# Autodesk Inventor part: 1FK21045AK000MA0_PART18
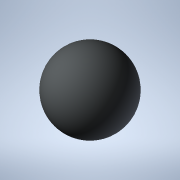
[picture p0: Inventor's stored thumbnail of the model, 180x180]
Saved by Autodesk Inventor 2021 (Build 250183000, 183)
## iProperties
Created: 2025-04
Part Number: 1FK21045AK000MA0_PART18
Material: Generic
Catalog Web Link: www.3dfindit.com
Description: -Servo synchronous motor
Document SubType Name: Modeling
Designer: psAdmin
Mass: 0.137258 g
Surface Area: 1.2868 cm^2
Volume: 0.137258 cm^3
Density: 1 g/cm^3
Appearance: PSOLRGB-212-217-219
Category: PARTsolutions
Title: 1FK21045AK000MA0_PART18
Author: Cadenas PARTsolutions
Comments: Servo synchronous motor
Sending System: PARTsolutions
Preprocessor: ST-DEVELOPER v19.3
PSOL_IDENT_0: {$CADENAS_DATA/23d-libs/siemens_ag/_cat_/3d/2f/1fk21045ak000ma0.prj},216 {VTYP=3D},{NB=1FK21045AK000
PSOL_IDENT_1: MA0_PART18},{LINA=1FK21045AK000MA0_PART18},{NN=1FK21045AK000MA0_PART18},{NOPRJ=TRUE},{DATE=19.08.202
PSOL_IDENT_2: 5 14:00:34},{GEOMDATE=30.07.2025 02:01:24},{VERSION=},{LINEID=10},{WBVAR=},{WBNUMERIC=}  {NB=1FK2104
PSOL_IDENT_3: 5AK000MA0_PART18},{LINA=1FK21045AK000MA0_PART18},{KT=DUMMY},{PREVIEW=../../../_pool_/a9/69/p_d211_xx
PSOL_IDENT_4: _00818j.png},{DESCSHORT=SIMOTICS S-1FK2 HD, SINAMICS S210 3AC 400V-480V, 1.7 Nm, 6000 rpm},{DESCLONG=
PSOL_IDENT_5: SIMOTICS S-1FK2 HD servo motor M0=2.4 Nm; PN = 1.07 kW at nN=6000 rpm (380-480 V); PN = 0.75 kW at n
PSOL_IDENT_6: N=3000 rpm (200-240 V); degree of protection IP64; cylindrical shaft D19x40mm; absolute encoder 22-b
PSOL_IDENT_7: it + 12-bit multiturn (encoder AM22DQC); with OCC interface; plug size M17, rotatable; SIMOTICS S-1F
PSOL_IDENT_8: K2 servomotorfor a wide range of uses in industrial environments. SIMOTICS S‑1FK2 servomotors are co
PSOL_IDENT_9: mpact synchronous motors with a high dynamic performance that set themselves apart as a result of th
PSOL_IDENT_10: eir high power density, degree of protection and overload capability. The motors are available in tw
PSOL_IDENT_11: o variants: as High Dynamic variant (highest dynamic performance as a result of the low intrinsic mo
PSOL_IDENT_12: ment of inertia for applications demanding a high dynamic performance with low moved masses) - and a
PSOL_IDENT_13: s Compact variant (precise and stable closed-loop control for medium up to large moved masses as a r
PSOL_IDENT_14: esult of a medium intrinsic moment of inertia). SIMOTICSS‑1FK2 servomotors fully exploit their stren
PSOL_IDENT_15: gths in a system with the SINAMICSS210 frequency converter and simple connection using the one cable
PSOL_IDENT_16: connection (OCC). Advantages include the short control and positioning times, fast and precise corr
PSOL_IDENT_17: ection of disturbing quantities as well as stable control with a high dynamic performance. The servo
PSOL_IDENT_18: motors can be configured to address a wide range of requirements. For example with and without hold
PSOL_IDENT_19: ing brake, IP64 or IP65 degree of protection, singleturn or multiturn absolute encoders - to name ju
PSOL_IDENT_20: st a few. Further, the servomotors are available in different shaft heights extending from 20 to 100
PSOL_IDENT_21: . A shaft sealing ring is available to achieve an IP65 degree of protection and for subsequent mount
PSOL_IDENT_22: ing at the motor or as spare part. SIMOTICS - the optimum motor for each and every motion control ap
PSOL_IDENT_23: plication.},{INTNO=804766789342},{SUPPLIERALTNO=1FK2104-5AK00-0MA0},{MANUID=1FK21045AK000MA0},{MANUN
PSOL_IDENT_24: AME=Siemens},{MANUTYPEDESC=Synchronous motor 1FK2-HD 2,39 Nm},{AAU732=SIMOTICS},{AAO057=S-1FK2},{AAU
PSOL_IDENT_25: 734=SIMOTICS S-1FK2 HD servo motor M0=2.4 Nm; PN = 1.07 kW at nN=6000 rpm (380-480 V); PN = 0.75 kW
PSOL_IDENT_26: at nN=3000 rpm (200-240 V); degree of protection IP64; cylindrical shaft D19x40mm; absolute encoder
PSOL_IDENT_27: 22-bit + 12-bit multiturn (encoder AM22DQC); with OCC interface; plug size M17, rotatable;},{AAW338=
PSOL_IDENT_28: Synchronous motor 1FK2-HD 2,39 Nm},{AAO742=SIMOTICS},{AAO663=4042948691151},{NOCUPEROU=1},{PRICEQUAN
PSOL_IDENT_29: TITY=1},{QUANTITYMIN=1},{QUANTITYINT=1},{CTN=85015100},{COO=DE},{AAO676=1FK2104-5AK00-0MA0},{AAO677=
PSOL_IDENT_30: Siemens AG},{ORDERUNIT=C62},{CONTENTUNIT=C62}
NB: 1FK21045AK000MA0_PART18
NT: Servo synchronous motor
NBSYN: $MANUID._PART18
LINA: 1FK21045AK000MA0_PART18
CATALOG: SIEMENS
PREVIEW: ../../../_pool_/a9/69/p_d211_xx_00818j.png
DESCSHORT: SIMOTICS S-1FK2 HD, SINAMICS S210 3AC 400V-480V, 1.7 Nm, 6000 rpm
DESCLONG: SIMOTICS S-1FK2 HD servo motor M0=2.4 Nm; PN = 1.07 kW at nN=6000 rpm (380-480 V); PN = 0.75 kW at nN=3000 rpm (200-240 V); degree of protection IP64; cylindric
INTNO: 804766789342
SUPPLIERALTNO: 1FK2104-5AK00-0MA0
MANUID: 1FK21045AK000MA0
MANUNAME: Siemens
MANUTYPEDESC: Synchronous motor 1FK2-HD 2,39 Nm
AAU732: SIMOTICS
AAO057: S-1FK2
AAU734: SIMOTICS S-1FK2 HD servo motor M0=2.4 Nm; PN = 1.07 kW at nN=6000 rpm (380-480 V); PN = 0.75 kW at nN=3000 rpm (200-240 V); degree of protection IP64; cylindric
AAW338: Synchronous motor 1FK2-HD 2,39 Nm
AAO742: SIMOTICS
AAO663: 4042948691151.0
NOCUPEROU: 1
PRICEQUANTITY: 1
QUANTITYMIN: 1
QUANTITYINT: 1
CTN: 85015100
COO: DE
ARTICLENO: 1FK21045AK000MA0_PART18
BOMINFO: 1FK21045AK000MA0_PART18
CREATOR: CADENAS GmbH
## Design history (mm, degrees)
feature "2025_04_17_15_39_51_0728"
body "Solid1"
